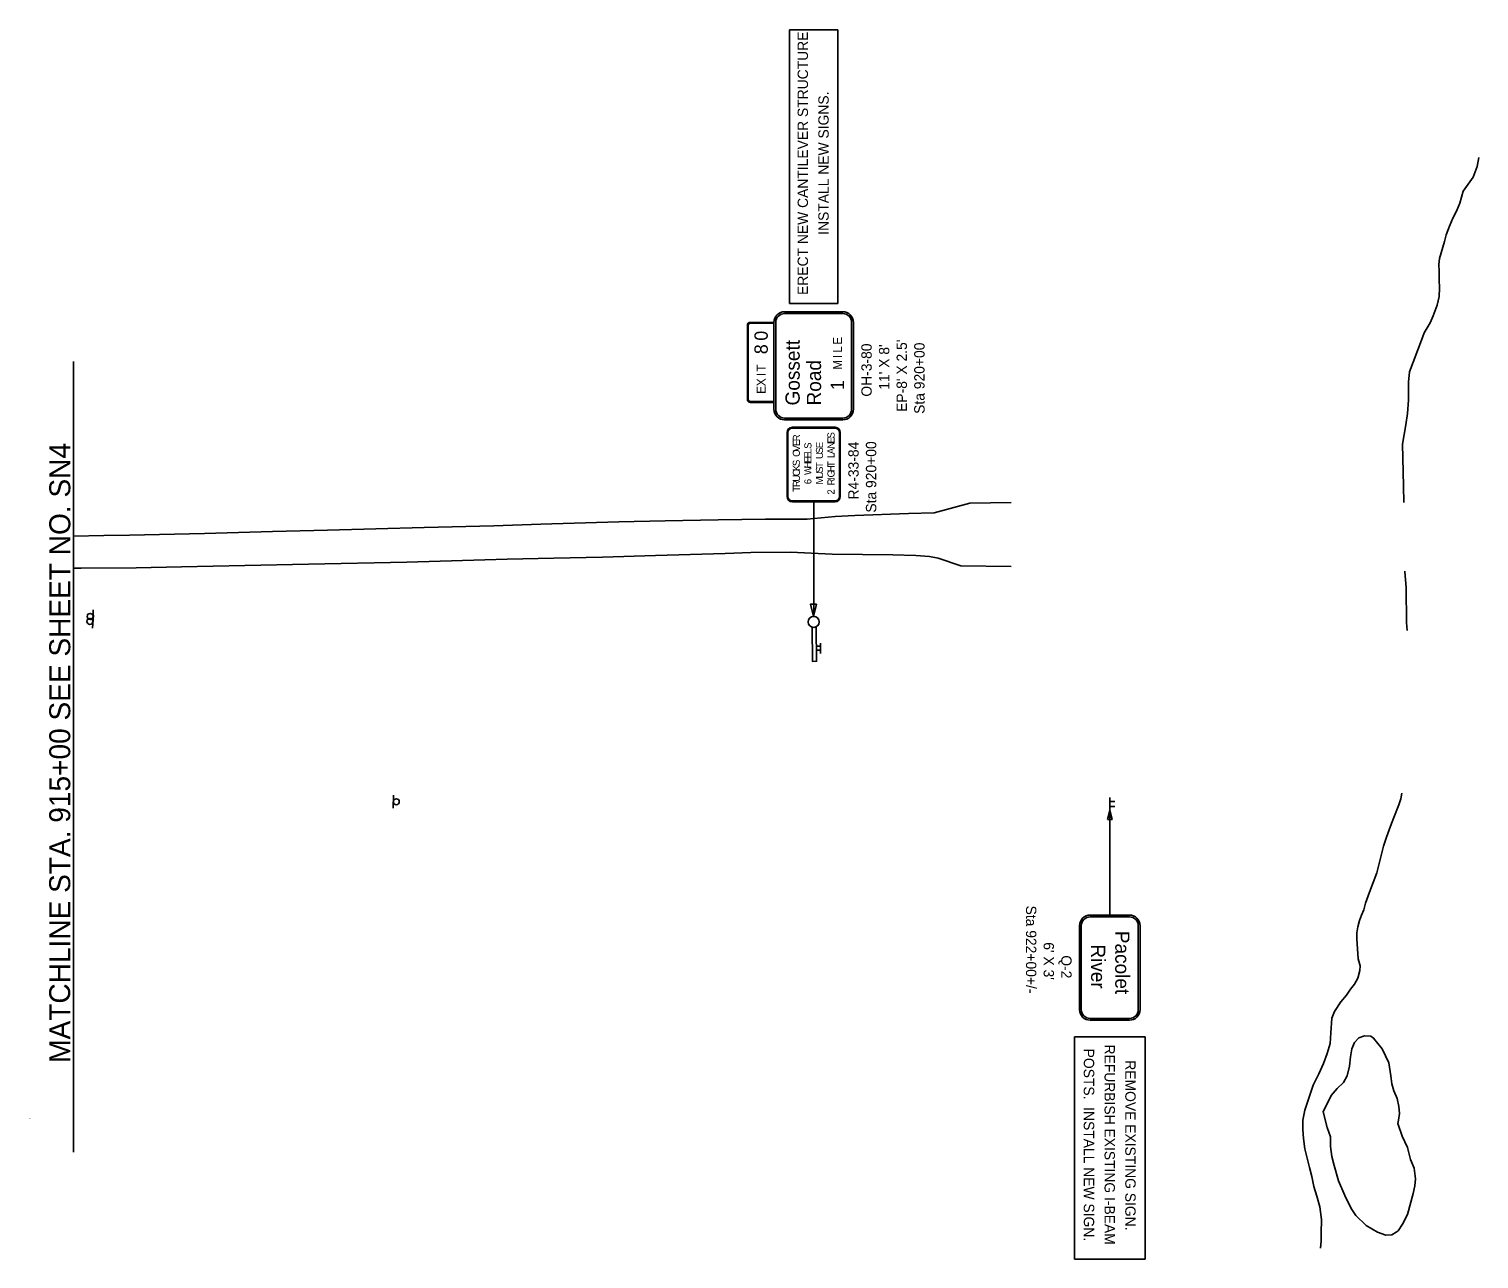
# Model space of a CAD drawing. Extents: x 1738774 to 1740659, y 1167903 to 1168804.
# Drawn here: x 1738774 to 1739753, y 1167974 to 1168804 of the extents above; entities that cross this region are included whole.
import ezdxf

# ---------------------------------------------------------------- set-up
doc = ezdxf.new("R2010")
doc.units = 0
for name, color, linetype in [('Default', 7, 'Continuous'), ('RD_EX_H2O', 7, 'Continuous'), ('RD_EX_Road', 7, 'Continuous'), ('RD_SHT_MatchLine', 7, 'Continuous'), ('RD_SHT_TX', 7, 'Continuous'), ('SN_P_Signs', 7, 'Continuous')]:
    doc.layers.add(name, color=color, linetype=linetype)

msp = doc.modelspace()

# ---------------------------------------------------------------- linework, layer by layer
at = {"layer": 'RD_EX_H2O'}
for points in [[(1739753.1, 1168717.77), (1739751.8, 1168711.49), (1739749.22, 1168704.4), (1739742.38, 1168694.93), (1739741.25, 1168690.82), (1739740.25, 1168686.87), (1739737.91, 1168681.33), (1739735.53, 1168676.76), (1739733.19, 1168671.22), (1739730.99, 1168665.55), (1739729.74, 1168660.88), (1739726.46, 1168649.56), (1739725.89, 1168645.34), (1739726.17, 1168641.01), (1739726.22, 1168635.26), (1739726.41, 1168629.39), (1739726.31, 1168623.78), (1739724.82, 1168617.85), (1739722.11, 1168610.62), (1739720.01, 1168606.07), (1739716.17, 1168599.36), (1739714.23, 1168594.25), (1739706.24, 1168572.85), (1739705.48, 1168565.96), (1739705.59, 1168553.78), (1739704.76, 1168544.8), (1739703.61, 1168537.06), (1739701.5, 1168524.11), (1739702.21, 1168495.87), (1739702.38, 1168484.69)], [(1739703.09, 1168438.32), (1739703.09, 1168438.09), (1739704.01, 1168426.93), (1739704.2, 1168403.71), (1739704.6, 1168398.12)], [(1739700.95, 1168288.33), (1739700.21, 1168284.46), (1739698.94, 1168280.51), (1739695.58, 1168272.02), (1739693.25, 1168266.07), (1739690.56, 1168258.58), (1739688.52, 1168252.51), (1739686.68, 1168244.48), (1739684.07, 1168234.62), (1739679.04, 1168221.47), (1739676.49, 1168213.98), (1739675.24, 1168209.47), (1739673.68, 1168205.93), (1739672.39, 1168202.4), (1739671.27, 1168198.17), (1739670.57, 1168194.1), (1739670.7, 1168190.05), (1739671.55, 1168176.4), (1739672.73, 1168171.69), (1739672.69, 1168168.48), (1739671.32, 1168163.4), (1739669.07, 1168159.28), (1739666.25, 1168155.98), (1739663.58, 1168151.98), (1739659.68, 1168147.39), (1739655.56, 1168140.83), (1739653.76, 1168136.31), (1739653.09, 1168126.51), (1739652.63, 1168119.23), (1739650.61, 1168112.47), (1739648.03, 1168105.82), (1739644.91, 1168098.88), (1739641.11, 1168091.22), (1739635.51, 1168074.29), (1739634.06, 1168067.41), (1739634.11, 1168061.27), (1739634.59, 1168055.14), (1739635.38, 1168048.05), (1739638.57, 1168035.46), (1739640.3, 1168029.52), (1739641.49, 1168022.72), (1739643.66, 1168016.09), (1739645.56, 1168009.04), (1739646.68, 1168000.29), (1739646.56, 1167991.08), (1739646.44, 1167986.05), (1739645.94, 1167980.98)], [(1739658.25, 1168026.47), (1739655.26, 1168036.97), (1739653.81, 1168043.06), (1739652.77, 1168049.59), (1739652.83, 1168056.29), (1739650.54, 1168062.5), (1739647.83, 1168073.01), (1739653.19, 1168084.21), (1739657.36, 1168088.95), (1739661.56, 1168092.86), (1739664.06, 1168097.54), (1739665.67, 1168104.02), (1739666.31, 1168110.32), (1739667.11, 1168115.65), (1739668.93, 1168119.9), (1739672.04, 1168123.07), (1739675.76, 1168124.45), (1739679.96, 1168124.3), (1739681.95, 1168122.97), (1739687.63, 1168115.75), (1739692.13, 1168106.13), (1739693.53, 1168097.38), (1739694.25, 1168092.09), (1739695.67, 1168087.25), (1739697.93, 1168082.02), (1739698.94, 1168076.75), (1739699.51, 1168071.89), (1739698.81, 1168067.54), (1739698.33, 1168065.15), (1739701.11, 1168056.73), (1739704.71, 1168049.03), (1739706.92, 1168041.01), (1739709.34, 1168035.09), (1739710.14, 1168027.86), (1739709.87, 1168023.24), (1739708.64, 1168017.9), (1739704.78, 1168003.69), (1739701.5, 1167997.17), (1739698.43, 1167992.75), (1739697.07, 1167991.87), (1739694.2, 1167990.1), (1739690.16, 1167989.83), (1739684.66, 1167991.75), (1739676.84, 1167996.24), (1739669.93, 1168002.99), (1739666.7, 1168007.91), (1739662.38, 1168016.69), (1739658.25, 1168026.47)]]:
    msp.add_lwpolyline(points, dxfattribs=at)
at = {"layer": 'RD_EX_Road'}
for points in [[(1739437.16, 1168484.65), (1739409.21, 1168484.18), (1739385.19, 1168477.68), (1739367.82, 1168477.16), (1739331.5, 1168475.9), (1739318.31, 1168475.09), (1739299.4, 1168473.51), (1739271.11, 1168473.32), (1739239.32, 1168472.88), (1739203.32, 1168472.31), (1739172.18, 1168471.53), (1739119.5, 1168470.07), (1739087.73, 1168468.97), (1739040.53, 1168467.68), (1738975.43, 1168465.87), (1738938.26, 1168464.99), (1738892.36, 1168463.75), (1738841.72, 1168462.57), (1738824.32, 1168462.37), (1738803.73, 1168461.86)], [(1738803.73, 1168440.28), (1738808.89, 1168440.3), (1738846.15, 1168440.51), (1738876.81, 1168441.16), (1738919.59, 1168442.02), (1738962.52, 1168443.02), (1739028.88, 1168444.47), (1739081.68, 1168445.92), (1739096.65, 1168446.45), (1739128.12, 1168447.16), (1739161.15, 1168447.84), (1739196.86, 1168448.88), (1739243.89, 1168450.18), (1739261.33, 1168450.81), (1739288.18, 1168451.1), (1739316.24, 1168449.82), (1739357.13, 1168449.34), (1739372.67, 1168448.84), (1739381.9, 1168448.21), (1739387.89, 1168447.02), (1739403.15, 1168441.8), (1739437.22, 1168441.51)]]:
    msp.add_lwpolyline(points, dxfattribs=at)
at = {"layer": 'RD_SHT_MatchLine'}
msp.add_lwpolyline([(1738803.73, 1168045.77), (1738803.73, 1168344.04), (1738803.73, 1168579.79)], dxfattribs=at)
at = {"layer": 'SN_P_Signs'}
for p, q in [((1739287.33, 1168619.03), (1739287.33, 1168803.98)), ((1739287.33, 1168803.98), (1739320.14, 1168803.98)), ((1739320.14, 1168803.98), (1739320.14, 1168619.03)), ((1739320.14, 1168619.03), (1739287.33, 1168619.03)), ((1739303.73, 1168485.08), (1739303.73, 1168407.75)), ((1738816.57, 1168399.68), (1738817.25, 1168408.65)), ((1738816.88, 1168403.16), (1738817.12, 1168412.16)), ((1739308.28, 1168389.7), (1739308.36, 1168382.74)), ((1739305.55, 1168387.57), (1739308.32, 1168387.6)), ((1739305.58, 1168384.89), (1739308.36, 1168384.92)), ((1739019.88, 1168287.09), (1739019.72, 1168278.1)), ((1739503.73, 1168276.69), (1739503.73, 1168285.39)), ((1739503.73, 1168282.65), (1739507.06, 1168282.65)), ((1739503.73, 1168279.3), (1739507.06, 1168279.3)), ((1739503.73, 1168276.69), (1739503.73, 1168206.01)), ((1739524.17, 1168198.81), (1739524.17, 1168142.2)), ((1739479.93, 1167973.72), (1739479.93, 1168123.74)), ((1739479.93, 1168123.74), (1739527.54, 1168123.74)), ((1739527.54, 1168123.74), (1739527.54, 1167973.72)), ((1739527.54, 1167973.72), (1739479.93, 1167973.72))]:
    msp.add_line(p, q, dxfattribs=at)
for points in [[(1739284.12, 1168613.48), (1739323.35, 1168613.48)], [(1739258.92, 1168554.08), (1739258.92, 1168604.48)], [(1739259.52, 1168604.48), (1739259.52, 1168554.08)], [(1739260.72, 1168606.28), (1739276.92, 1168606.28), (1739276.92, 1168605.68)], [(1739276.92, 1168605.68), (1739260.72, 1168605.68)], [(1739276.92, 1168547.68), (1739276.92, 1168606.28)], [(1739278.12, 1168547.68), (1739278.12, 1168606.28)], [(1739284.12, 1168612.28), (1739323.35, 1168612.28)], [(1739329.35, 1168606.28), (1739329.35, 1168547.68)], [(1739330.55, 1168606.28), (1739330.55, 1168547.68)], [(1739260.72, 1168552.88), (1739276.92, 1168552.88), (1739276.92, 1168552.28), (1739260.72, 1168552.28)], [(1739323.35, 1168541.68), (1739284.12, 1168541.68)], [(1739323.35, 1168540.48), (1739284.12, 1168540.48)], [(1739318.13, 1168535.48), (1739289.33, 1168535.48)], [(1739285.73, 1168531.88), (1739285.73, 1168488.68)], [(1739286.33, 1168488.68), (1739286.33, 1168531.88)], [(1739289.33, 1168534.88), (1739318.13, 1168534.88)], [(1739321.13, 1168531.88), (1739321.13, 1168488.68)], [(1739321.73, 1168488.68), (1739321.73, 1168531.88)], [(1739318.13, 1168485.68), (1739289.33, 1168485.68)], [(1739289.33, 1168485.08), (1739318.13, 1168485.08)], [(1739302.61, 1168400.51), (1739302.87, 1168377.38), (1739305.66, 1168377.41), (1739305.4, 1168400.72)], [(1739490.5, 1168206.01), (1739516.97, 1168206.01)], [(1739490.5, 1168204.81), (1739516.97, 1168204.81)], [(1739483.3, 1168142.2), (1739483.3, 1168198.81)], [(1739484.5, 1168142.2), (1739484.5, 1168198.81)], [(1739522.97, 1168198.81), (1739522.97, 1168142.2)], [(1739516.97, 1168136.2), (1739490.5, 1168136.2)], [(1739516.97, 1168135), (1739490.5, 1168135)]]:
    msp.add_lwpolyline(points, dxfattribs=at)
for points in [[(1739305.65, 1168415.98), (1739303.69, 1168407.75), (1739301.55, 1168415.93)], [(1739502.2, 1168270.54), (1739503.73, 1168276.69), (1739505.27, 1168270.54)]]:
    msp.add_lwpolyline(points, close=True, dxfattribs=at)
for centre, radius in [((1738814.98, 1168407.73), 2), ((1738814.89, 1168404.34), 2), ((1739303.73, 1168404.04), 3.71), ((1739021.82, 1168282.54), 2)]:
    msp.add_circle(centre, radius, dxfattribs=at)
for centre, radius, start, end in [((1739284.12, 1168606.28), 7.2, 90, 180), ((1739323.35, 1168606.28), 7.2, 360, 90), ((1739260.72, 1168604.48), 1.8, 90, 180), ((1739260.72, 1168604.48), 1.2, 90, 180), ((1739284.12, 1168606.28), 6, 90, 180), ((1739323.35, 1168606.28), 6, 360, 90), ((1739260.72, 1168554.08), 1.8, 180, 270), ((1739260.72, 1168554.08), 1.2, 180, 270), ((1739284.12, 1168547.68), 7.2, 180, 270), ((1739284.12, 1168547.68), 6, 180, 270), ((1739323.35, 1168547.68), 6, 270, 360), ((1739323.35, 1168547.68), 7.2, 270, 360), ((1739289.33, 1168531.88), 3.6, 90, 180), ((1739318.13, 1168531.88), 3.6, 360, 90), ((1739289.33, 1168531.88), 3, 90, 180), ((1739318.13, 1168531.88), 3, 360, 90), ((1739289.33, 1168488.68), 3.6, 180, 270), ((1739289.33, 1168488.68), 3, 180, 270), ((1739318.13, 1168488.68), 3.6, 270, 360), ((1739318.13, 1168488.68), 3, 270, 360), ((1739490.5, 1168198.81), 7.2, 90, 180), ((1739490.5, 1168198.81), 6, 90, 180), ((1739516.97, 1168198.81), 7.2, 0, 90), ((1739516.97, 1168198.81), 6, 0, 90), ((1739490.5, 1168142.2), 7.2, 180, 270), ((1739490.5, 1168142.2), 6, 180, 270), ((1739516.97, 1168142.2), 6, 270, 0), ((1739516.97, 1168142.2), 7.2, 270, 0)]:
    msp.add_arc(centre, radius, start, end, dxfattribs=at)

# ---------------------------------------------------------------- texts
at = {"layer": 'Default'}
for s, height, p in [('Angle:  16.0848', 0.2083, (1738773.73, 1168068.56)), ('Align: A_I85', 0.2083, (1738773.73, 1168068.29)), ('Sheet: 5', 0.208, (1738773.73, 1168068.83))]:
    msp.add_text(s, height=height, dxfattribs=at).set_placement(p)
at = {"layer": 'RD_SHT_TX'}
msp.add_text('MATCHLINE STA. 915+00 SEE SHEET NO. SN4', height=14.1726, rotation=89.98556, dxfattribs=at).set_placement((1738801.54, 1168106.21))
at = {"layer": 'SN_P_Signs'}
for s, height, rotation, p in [('ERECT NEW CANTILEVER STRUCTURE.', 7, 90.00008, (1739299.88, 1168624.85)), ('INSTALL NEW SIGNS.', 7, 90.00008, (1739313.88, 1168665.47)), ('0', 9, 90, (1739272.72, 1168593.94)), ('Gossett', 9.6, 90, (1739294.29, 1168550.18)), ('E', 6, 90, (1739322.81, 1168591.19)), ("EP-8' X 2.5'", 7, 90.00008, (1739366.72, 1168545.84)), ('8', 9, 90, (1739272.72, 1168584.84)), ('L', 6, 90, (1739322.81, 1168585.77)), ('OH-3-80', 7, 90.00008, (1739342.92, 1168556.15)), ("11' X 8'", 7, 90.00008, (1739354.82, 1168560.83)), ('Sta 920+00', 7, 90.00008, (1739378.62, 1168544.52)), ('T', 6, 90, (1739271.22, 1168572.97)), ('Road', 9.6, 90, (1739308.71, 1168550.18)), ('I', 6, 90, (1739322.81, 1168582.18)), ('M', 6, 90, (1739322.81, 1168574.31)), ('I', 6, 90, (1739271.22, 1168569.98)), ('X', 6, 90, (1739271.22, 1168563.17)), ('1', 9, 90, (1739324.31, 1168560.57)), ('E', 6, 90, (1739271.22, 1168558.02)), ('R', 4.8, 90, (1739294.43, 1168526.02)), ('E', 4.8, 90, (1739294.43, 1168522.81)), ('E', 4.8, 90, (1739310.03, 1168521.31)), ('S', 4.8, 90, (1739317.83, 1168527.94)), ('E', 4.8, 90, (1739317.83, 1168524.73)), ('R4-33-84', 7, 90.00008, (1739334.11, 1168486.69)), ('Sta 920+00', 7, 90.00008, (1739346.01, 1168477.82)), ('O', 4.8, 90, (1739294.43, 1168515.49)), ('V', 4.8, 90, (1739294.43, 1168519.08)), ('S', 4.8, 90, (1739302.23, 1168520.92)), ('L', 4.8, 90, (1739302.23, 1168517.71)), ('E', 4.8, 90, (1739302.23, 1168514.5)), ('S', 4.8, 90, (1739310.03, 1168517.68)), ('U', 4.8, 90, (1739310.03, 1168514.04)), ('N', 4.8, 90, (1739317.83, 1168521.1)), ('A', 4.8, 90, (1739317.83, 1168517.29)), ('L', 4.8, 90, (1739317.83, 1168514.61)), ('S', 4.8, 90, (1739294.43, 1168509.27)), ('C', 4.8, 90, (1739294.43, 1168502.4)), ('K', 4.8, 90, (1739294.43, 1168505.83)), ('E', 4.8, 90, (1739302.23, 1168511.29)), ('H', 4.8, 90, (1739302.23, 1168507.65)), ('W', 4.8, 90, (1739302.23, 1168503.24)), ('S', 4.8, 90, (1739310.03, 1168504.61)), ('T', 4.8, 90, (1739310.03, 1168508.04)), ('G', 4.8, 90, (1739317.83, 1168501.54)), ('T', 4.8, 90, (1739317.83, 1168508.61)), ('H', 4.8, 90, (1739317.83, 1168505.18)), ('U', 4.8, 90, (1739294.43, 1168498.76)), ('R', 4.8, 90, (1739294.43, 1168495.12)), ('6', 4.8, 90, (1739302.23, 1168497.02)), ('U', 4.8, 90, (1739310.03, 1168500.97)), ('M', 4.8, 90, (1739310.03, 1168496.85)), ('I', 4.8, 90, (1739317.83, 1168499.86)), ('R', 4.8, 90, (1739317.83, 1168496.22)), ('T', 4.8, 90, (1739294.43, 1168491.91)), ('2', 4.8, 90, (1739317.83, 1168490)), ('Sta 922+00+/-', 7, 270.00008, (1739447.13, 1168212.4)), ('Pacolet', 9.6, 270, (1739507.42, 1168195.36)), ("6' X 3'", 7, 270.00008, (1739459.03, 1168187.65)), ('River', 9.6, 270, (1739491.1, 1168186.22)), ('Q-2', 7, 270.00008, (1739470.93, 1168178.83)), ('POSTS.  INSTALL NEW SIGN.', 6.9998, 270.00008, (1739486.18, 1168115.79)), ('REFURBISH EXISTING I-BEAM', 6.9998, 270.00008, (1739500.18, 1168118.56)), ('REMOVE EXISTING SIGN.', 6.9998, 270.00008, (1739514.18, 1168107.91))]:
    msp.add_text(s, height=height, rotation=rotation, dxfattribs=at).set_placement(p)

doc.saveas('drawing.dxf')
